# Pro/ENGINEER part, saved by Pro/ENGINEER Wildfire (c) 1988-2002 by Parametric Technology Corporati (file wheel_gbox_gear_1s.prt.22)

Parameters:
  PTNUM = "A_1C_1MYK20060"
  PTNAME = "HUBLESS_SPUR_GEAR_WITHOUT_KEYWAY-MODULE_2.0"
  MFG = "STOCK_DRIVE_PRODUCTS"
  WEIGHT = "*"
  MATERIAL = "STEEL"

Other parameters: TEETH, MODULE, OUTSIDE_DIA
